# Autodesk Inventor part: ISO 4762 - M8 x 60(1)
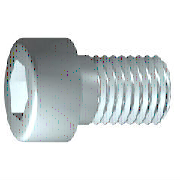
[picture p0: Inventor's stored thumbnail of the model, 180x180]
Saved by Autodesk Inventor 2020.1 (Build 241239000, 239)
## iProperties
Created: 2019-01
Part Number: ISO 4762 - M8 x 60(1)
Material: Edelstahl, 440C
Description: Innensechskantschraube
Document SubType Name: Modeling
Standard: ISO 4762
Designer: lutzd
Standard Revision: Fourth edition 2004-03-01
Standards Organization: ISO
Language: de-DE
Size Designation: M8 x 60
Categories: <MemberInstance><Categories><Category DisplayName="Verbindungselemente" InternalName="e4da775c-781d-43d5-af7c-5136215cf5a6" Mnemonic="FSTN"><Category DisplayNam
Mass: 30.3515 g
Surface Area: 21.6434 cm^2
Volume: 3.91632 cm^3
Density: 7.75 g/cm^3
Appearance: Semi-Polished(3)
IsCustomPart: 0
Author: lutzd
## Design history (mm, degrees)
workplane "Work Plane1"
fillet "Fillet2" dims "d30" = 0.1 (= R)
sketch "Skizze1"
  geometry: L1 (-2, 0)-(60, 0); L2 (60, 0)-(60, 4); L3 (60, 4)-(32, 4); L4 (32, 4)-(31.233, 4); L5 (31.233, 4)-(0, 4); L6 (0, 4)-(0, 6.5); L7 (0, 6.5)-(-8, 6.5); L8 (-8, 6.5)-(-8, 3.464); L9 (-8, 3.464)-(-4, 3.464); L10 (-4, 3.464)-(-2, 0); L11 (-21.6, 0)-(73.6, 0) reference; L12 (0, -1.3)-(0, 7.8) reference; L13 (32, 4)-(0, 4)
  constraints: 22 end point, 6 parallel, 2 collinear, 2 perpendicular, 1 horizontal, 1 point on line
  dimensions: "d1" = 28 distance from line of L3.end L2 (= GEL); "d2" = 0.76691 distance of L4.end L3.end (computed from GAL); "d3" = 8 distance between parallel lines of L8 L6 (= KOH); "d4" = 4 distance of L8.end L9.end (= INTI); "d5" = 60 deg angle of L10 L1; "d6" = 8 diameter of L3 L1 (= GD); "d7" = 8 diameter of L5 L1 (= BDM); "d8" = 6.9282 diameter of L9 L1 (= 1.1547 x SW); "d9" = 13 diameter of L7 L1 (= KOD); "d26" = 60 distance between parallel lines of L12 L2 (= NLG)
revolve "Körper" sketch "Skizze1" stored, may be unused: angle "d10" = 90 deg
sketch "Skizze2"
  geometry: L1 (0, -9.1)-(0, 9.1) reference; L2 (-9.1, 0)-(9.1, 0) reference; L3 (3.464, 0)-(1.732, -3); L4 (1.732, -3)-(-1.732, -3); L5 (-1.732, -3)-(-3.464, 0); L6 (-3.464, 0)-(-1.732, 3); L7 (-1.732, 3)-(1.732, 3); L8 (1.732, 3)-(3.464, 0); 2 further points
  constraints: 12 end point, 1 coincident, 1 horizontal alignment, 1 point on line, 12 other
extrude "Loch" join sketch "Skizze2" stored distance "d11" = 10; taper "d12" = 0 deg
body "Solid1"
fillet "Rundung1" dims "d17" = 0.8 (= RR)
feature "Gewinde" dims "d13" = 28 (= GEL), "d14" = 0
chamfer "Fase1" distance "d15" = 0.76681 (= -0.5 x SPD + 0.5 x GD); stored, may be unused: second distance "d16" = 0.76681 (= GUL), angle "d27" = 45 deg
other parameters: "GD" = 8 [user parameter; used in 2 equation terms], "NLG" = 60 [user parameter; used in 1 equation term], "GEL" = 28 [user parameter; used in 2 equation terms], "KOD" = 13 [user parameter; used in 1 equation term], "KOH" = 8 [user parameter; used in 1 equation term], "INTI" = 4 [user parameter; used in 1 equation term], "GAL" = 0.76681 (= 0.61345 x PTC) [user parameter; used in 1 equation term], "GUL" = 0.76681 (= 0.61345 x PTC) [user parameter; used in 1 equation term], "BDM" = 8 (= NND) [user parameter; used in 1 equation term], "SW" = 6 [user parameter; used in 2 equation terms], "RR" = 0.8 [user parameter; used in 1 equation term], "SPD" = 6.46637 (= NND - 1.2269 x PTC) [user parameter; used in 1 equation term], "d19" = 0, "d28" = 0, "d29" = 0, "R" = 0.1 [user parameter; used in 1 equation term], "TOA" = 30 deg [user parameter], "GD1" = 6.46637 (= THREADDIA - 1.2269 x PTC) [user parameter], "THREADDIA" = 8 [user parameter; used in 1 equation term], "FAWI" = 45 deg [user parameter], "TPU" = 8 (computed from PTC) [user parameter], "PTC" = 1.25 [user parameter; used in 5 equation terms], "NND" = 8 [user parameter; used in 2 equation terms], "E0" = 6.93 (= 1.155 x SW) [user parameter]
